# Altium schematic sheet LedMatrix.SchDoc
size A4; Organization: Altium Limited; Address1: L3, 12a Rodborough Rd; Address2: Frenchs Forest; Address3: NSW; Address4: Australia 2086
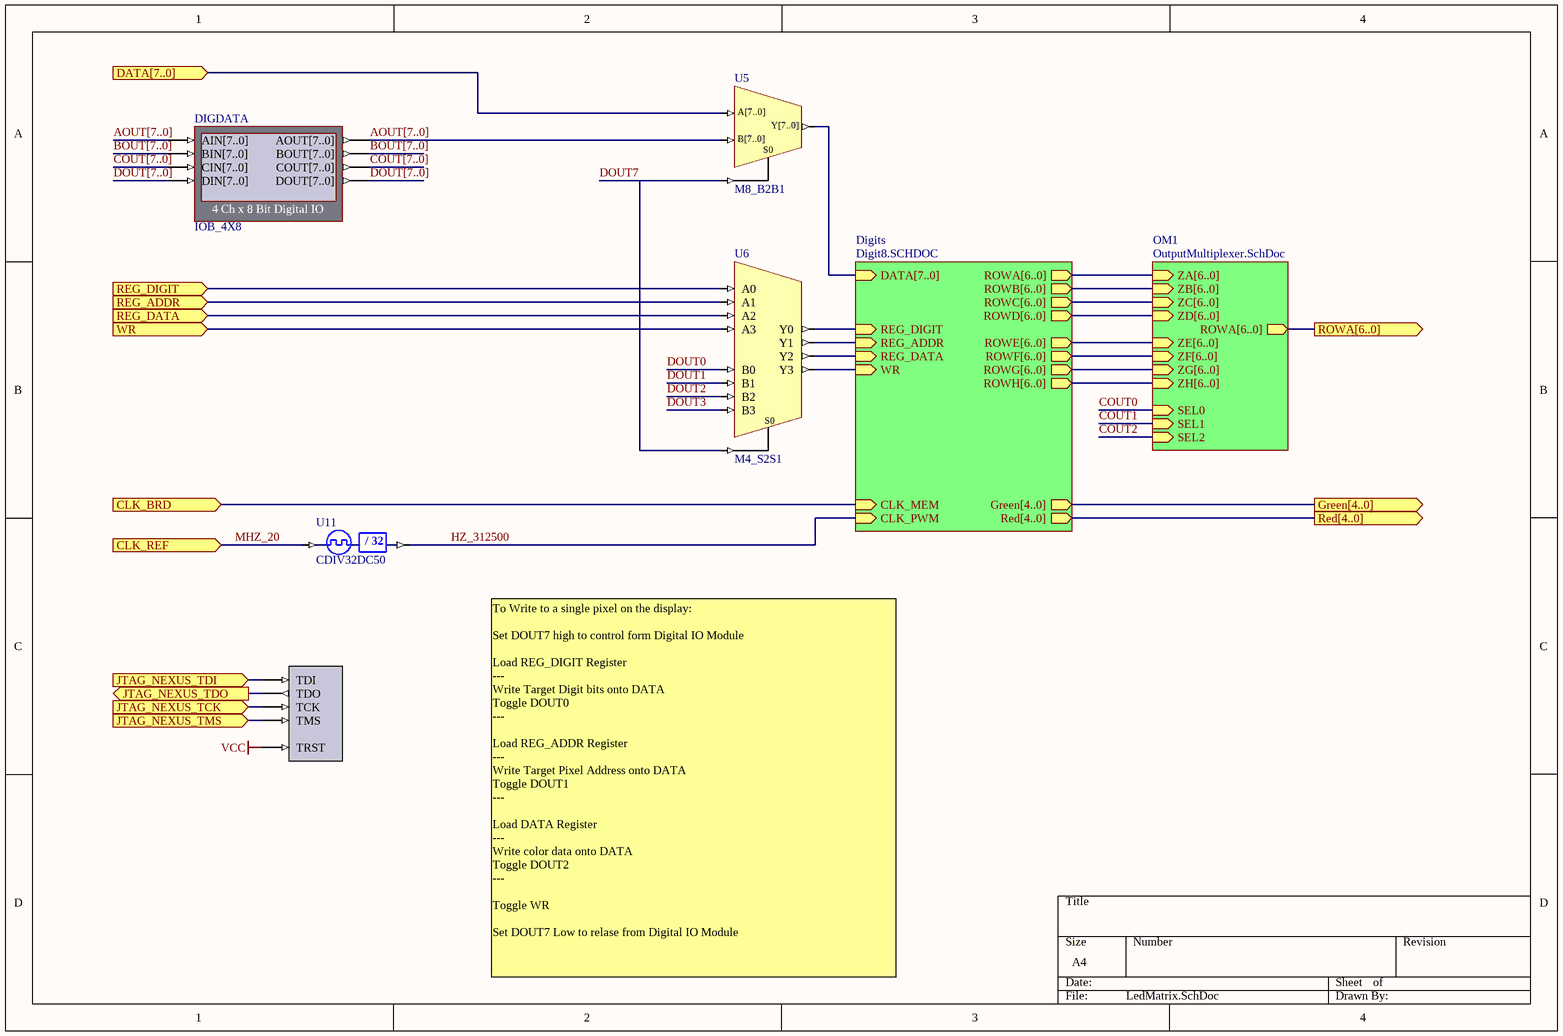
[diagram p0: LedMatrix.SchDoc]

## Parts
DIGDATA  IOB_4X8
NEXUS_JTAG_PORT1  NEXUS_JTAG_PORT  (value not drawn)
U5  M8_B2B1
U6  M4_S2S1
U11  CDIV32DC50

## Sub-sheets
Digits = Digit8.SCHDOC: ROWB[6..0] (out), ROWC[6..0] (out), ROWD[6..0] (out), ROWF[6..0] (out), ROWG[6..0] (out), ROWH[6..0] (out), ROWE[6..0] (out), ROWA[6..0] (out), CLK_MEM (in), CLK_PWM (in), DATA[7..0] (in), Red[4..0] (out), Green[4..0] (out), REG_DIGIT (in), REG_ADDR (in), REG_DATA (in), WR (in)
OM1 = OutputMultiplexer.SchDoc: ROWA[6..0] (out), SEL0 (in), SEL1 (in), SEL2 (in), ZB[6..0] (in), ZC[6..0] (in), ZD[6..0] (in), ZF[6..0] (in), ZG[6..0] (in), ZH[6..0] (in), ZE[6..0] (in), ZA[6..0] (in)

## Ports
CLK_BRD (in), CLK_REF (in), DATA[7..0] (in), Green[4..0] (out), JTAG_NEXUS_TCK (in), JTAG_NEXUS_TDI (in), JTAG_NEXUS_TDO (out), JTAG_NEXUS_TMS (in), Red[4..0] (out), REG_ADDR (in), REG_DATA (in), REG_DIGIT (in), ROWA[6..0] (out), WR (in)

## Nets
VCC: NEXUS_JTAG_PORT1.TRST
CLK_BRD: port CLK_BRD, sheet Digits/CLK_MEM
DOUT0: U6.B0
DOUT1: U6.B1
DOUT2: U6.B2
DOUT3: U6.B3
DOUT7: U5.S0 U6.S0
HZ_312500: U11.CLKDV ; sheet Digits/CLK_PWM
JTAG_NEXUS_TCK: NEXUS_JTAG_PORT1.TCK ; port JTAG_NEXUS_TCK
JTAG_NEXUS_TDI: NEXUS_JTAG_PORT1.TDI ; port JTAG_NEXUS_TDI
JTAG_NEXUS_TDO: NEXUS_JTAG_PORT1.TDO ; port JTAG_NEXUS_TDO
JTAG_NEXUS_TMS: NEXUS_JTAG_PORT1.TMS ; port JTAG_NEXUS_TMS
MHZ_20: U11.CLKIN ; port CLK_REF
REG_ADDR: U6.A1 ; port REG_ADDR
REG_DATA: U6.A2 ; port REG_DATA
REG_DIGIT: U6.A0 ; port REG_DIGIT
WR: U6.A3 ; port WR
NetU6_Y0: U6.Y0 ; sheet Digits/REG_DIGIT
NetU6_Y1: U6.Y1 ; sheet Digits/REG_ADDR
NetU6_Y2: U6.Y2 ; sheet Digits/REG_DATA
NetU6_Y3: U6.Y3 ; sheet Digits/WR

Not connected (* = marked no-connect by the designer): DIGDATA AIN[7..0] AOUT[7..0] BIN[7..0] BOUT[7..0] CIN[7..0] COUT[7..0] DIN[7..0] DOUT[7..0]; U5 A[7..0] B[7..0] Y[7..0]

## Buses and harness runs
bus AOUT[7..0]
bus BOUT[7..0]
bus COUT[7..0]
bus DOUT[7..0]
bus port Green[4..0] = sheet Digits/Green[4..0]
bus port Red[4..0] = sheet Digits/Red[4..0]
bus port ROWA[6..0] = sheet OM1/ROWA[6..0]
bus sheet Digits/ROWA[6..0] = sheet OM1/ZA[6..0]
bus sheet Digits/ROWB[6..0] = sheet OM1/ZB[6..0]
bus sheet Digits/ROWC[6..0] = sheet OM1/ZC[6..0]
bus sheet Digits/ROWD[6..0] = sheet OM1/ZD[6..0]
bus sheet Digits/ROWE[6..0] = sheet OM1/ZE[6..0]
bus sheet Digits/ROWF[6..0] = sheet OM1/ZF[6..0]
bus sheet Digits/ROWG[6..0] = sheet OM1/ZG[6..0]
bus sheet Digits/ROWH[6..0] = sheet OM1/ZH[6..0]

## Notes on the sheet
- To Write to a single pixel on the display:
  Set DOUT7 high to control form Digital IO Module
  Load REG_DIGIT Register
  ---
  Write Target Digit bits onto DATA
  Toggle DOUT0
  ---
  Load REG_ADDR Register
  ---
  Write Target Pixel Address onto DATA
  Toggle DOUT1
  ---
  Load DATA Register
  ---
  Write color data onto DATA
  Toggle DOUT2
  ---
  Toggle WR
  Set DOUT7 Low to relase from Digital IO Module

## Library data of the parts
DIGDATA = IOB_4X8: 4 Ch x 8 Bit Digital IO; NEXUS_CORE: Instrument; NEXUS_JTAG_DEVICE: True; NEXUS_JTAG_ORDER: 0
NEXUS_JTAG_PORT1 = NEXUS_JTAG_PORT: Nexus Processor JTAG Chain Connector; NEXUS_JTAG_CONNECTOR: True
U5 = M8_B2B1: 2x8-Bit Bus to 1x8-Bit Bus Multiplexer; ArchiveName: GENERIC
U6 = M4_S2S1: 2x4-Single Wire to 1x4-Single Wire Multiplexer; ArchiveName: GENERIC
U11 = CDIV32DC50: Clock Divider by 32 with 50% Duty Cycle Output; ArchiveName: GENERIC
